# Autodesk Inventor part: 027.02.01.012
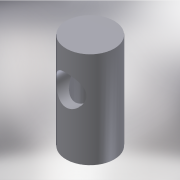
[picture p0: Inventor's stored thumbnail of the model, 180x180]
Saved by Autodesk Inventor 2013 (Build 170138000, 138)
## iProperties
Shininess: 64.0
Length Units: 11269
Angle Units: 11279
Time Units: 11290
Mass Units: 11283
Length Display Precision: 3
Angle Display Precision: 2
Created: 2003-04
Part Number: 027.02.01.012
Material: Steel, Mild
Document SubType Name: Modeling
Designer: NAndrey
Density: 1 g/cm^3
Density: 0.0
Volumn: 0.0
Area: 0.0
PropertySet Name: Model Information
Control State: 0
Master: False
Checked Out: True
Checked Out Date: 2008-10-15
Last Check In Date: 2008-10-15
Author: NAndrey
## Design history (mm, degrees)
sketch "Sketch1"
  geometry: C1 r 20 at (0, 0)
  constraints: 1 centre point
  dimensions: "d0" = 40 diameter of C1
extrude "Extrusion1" new body sketch "Sketch1" distance "d1" = 80; taper "d2" = 0 deg
sketch "Sketch2"
  geometry: C1 r 20 at (0, 0) reference
hole "Hole1" sketch "Sketch2" at (0, 0) diameter "d3" = 25; stored, may be unused: countersink angle "d7" = 82 deg, drill point angle "d9" = 120 deg; dims "d4" = 6, "d5" = 4, "d6" = 2, "d8" = 65
workaxis "Work Axis1"
workplane "Work Plane1"
workplane "Work Plane2"
sketch "Sketch3"
  geometry: L1 (0, 96)-(0, -16) reference; L2 (-20, 0)-(20, 0) reference; 1 further point
  constraints: 1 point on line
  dimensions: "d11" = 50 distance from line of point (0, 50) L2
hole "Hole2" sketch "Sketch3" at (0, 50) diameter "d12" = 25; stored, may be unused: countersink angle "d16" = 82 deg, drill point angle "d18" = 120 deg; dims "d13" = 6, "d14" = 4, "d15" = 2, "d17" = 20
body "Solid1"
other parameters: "d10" = 90 deg
